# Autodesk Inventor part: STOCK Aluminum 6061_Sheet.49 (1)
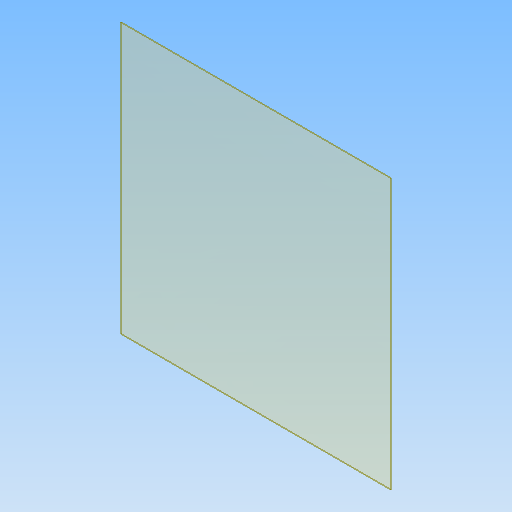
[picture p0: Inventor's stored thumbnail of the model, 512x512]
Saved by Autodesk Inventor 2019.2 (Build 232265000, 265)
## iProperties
Created: 2019-02
Part Number: STOCK Aluminum 6061_Sheet.49 (1)
Material: Aluminum 6061
Document SubType Name: Modeling
Designer: User
Density: 2.7 g/cm^3
Appearance: Aluminum - Flat
Author: User
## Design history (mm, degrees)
sketch "STOCK Aluminum 6061 sketch"
  geometry: L1 (0, 0)-(0, 533.4); L2 (0, 533.4)-(533.4, 533.4); L3 (533.4, 533.4)-(533.4, 0); L4 (533.4, 0)-(0, 0)
  constraints: 8 end point
extrude "STOCK Aluminum 6061 extrude" new body sketch "STOCK Aluminum 6061 sketch" stored distance "d0" = 1.5775; taper "d1" = 0 deg
node "STOCK Aluminum 6061"
